// Mitsubishi GX Works2 project: SK3U RS通讯   PLC: FX3U/FX3UC

PROGRAM MAIN
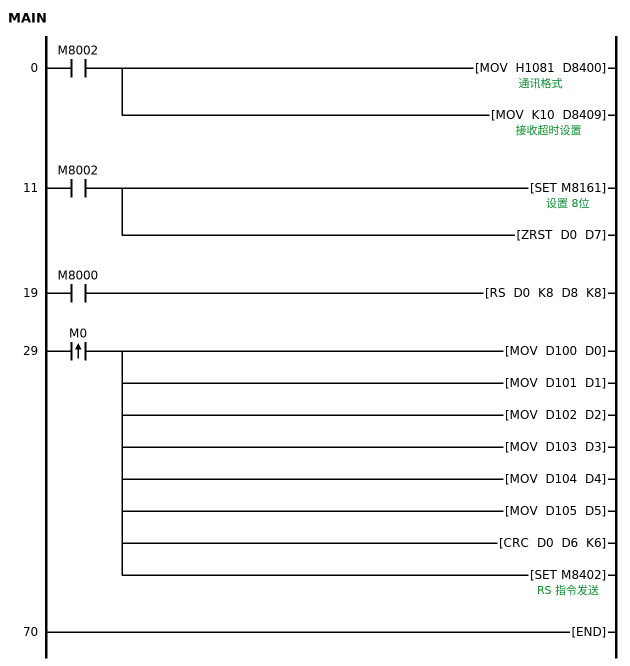
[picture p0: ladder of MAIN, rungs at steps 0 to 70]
0     LD      M8002
      MOV     H1081 D8400  ; 通讯格式
      MOV     K10 D8409  ; 接收超时设置
11    LD      M8002
      SET     M8161  ; 设置 8位
      ZRST    D0 D7
19    LD      M8000
      RS      D0 K8 D8 K8
29    LDP     M0
      MOV     D100 D0
      MOV     D101 D1
      MOV     D102 D2
      MOV     D103 D3
      MOV     D104 D4
      MOV     D105 D5
      CRC     D0 D6 K6
      SET     M8402  ; RS 指令发送
70    END
END_PROGRAM
